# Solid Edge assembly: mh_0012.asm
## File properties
Title: holder_unit
Author: edge
Template: normal.asm
Last saved by: edge
Revision: 38
Application: Solid Edge
Username: kiyo
文書内容のタイプ: 1
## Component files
mh_0026.asm
mh_0004.par
mh_0029.asm
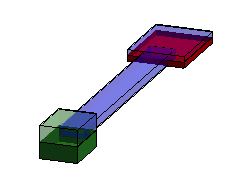
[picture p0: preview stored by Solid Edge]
